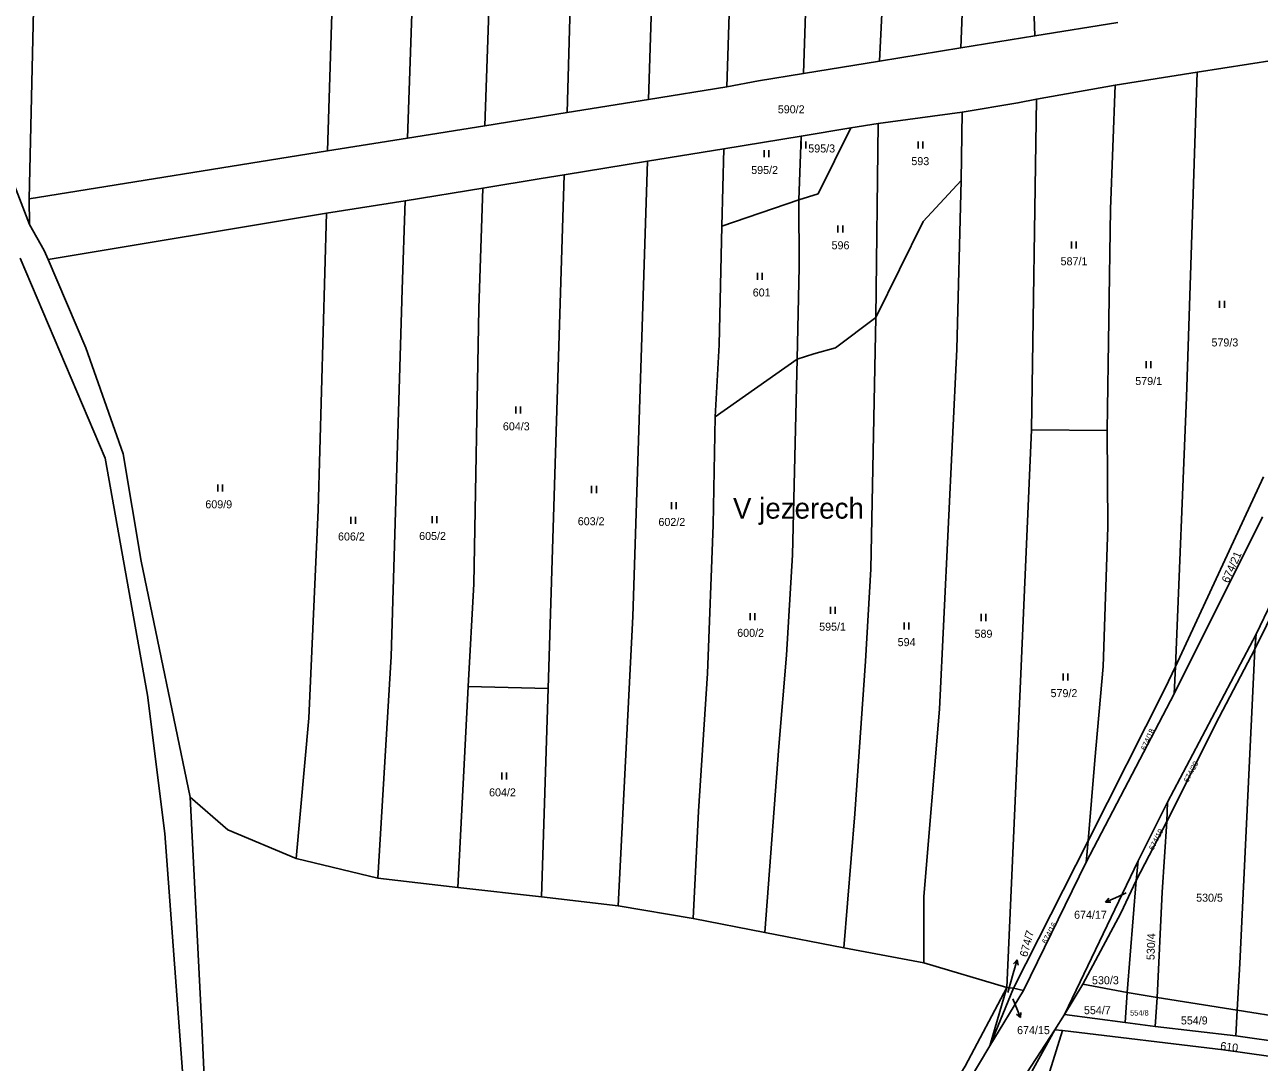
# Model space of a CAD drawing. Extents: x -7483133 to -743907, y -11317770 to -1129777.
# Drawn here: x -747219.6 to -746957.4, y -1132955.1 to -1132734.9 of the extents above; entities that cross this region are included whole.
import ezdxf

# ---------------------------------------------------------------- set-up
doc = ezdxf.new("R2010")
doc.units = 0
for name, color, linetype in [('Hranice parcel', 7, 'Continuous'), ('Parcelní čísla', 7, 'Continuous'), ('Pop  PČ popisy', 7, 'Continuous'), ('Značky kultur', 7, 'Continuous')]:
    doc.layers.add(name, color=color, linetype=linetype)

msp = doc.modelspace()

# ---------------------------------------------------------------- linework, layer by layer
at = {"layer": 'Hranice parcel'}
for p, q in [((-747020.76, -1132739.83), (-747018.91, -1132685.59)), ((-747005.69, -1132717.06), (-747005.08, -1132737.28)), ((-746987.48, -1132734.42), (-747005.08, -1132737.28)), ((-747005.08, -1132737.28), (-747020.76, -1132739.83)), ((-747020.76, -1132739.83), (-747038.08, -1132742.64)), ((-747038.08, -1132742.64), (-747054.23, -1132745.27)), ((-746970.6, -1132744.98), (-746954.26, -1132742.42)), ((-746970.6, -1132744.98), (-746988.01, -1132747.72)), ((-747070.51, -1132748.09), (-747087.14, -1132750.76)), ((-747004.75, -1132750.71), (-746988.01, -1132747.72)), ((-747087.14, -1132750.76), (-747104.4, -1132753.53)), ((-747004.75, -1132750.71), (-747005.78, -1132820.86)), ((-747104.4, -1132753.53), (-747121.84, -1132756.33)), ((-747038.33, -1132755.85), (-747020.5, -1132753.47)), ((-747020.5, -1132753.47), (-747020.75, -1132767.99)), ((-747121.84, -1132756.33), (-747138.3, -1132758.97)), ((-747054.69, -1132758.53), (-747044.17, -1132756.81)), ((-747044.17, -1132756.81), (-747038.33, -1132755.85)), ((-747038.33, -1132755.85), (-747038.87, -1132797.03)), ((-747138.3, -1132758.97), (-747155.28, -1132761.69)), ((-747071.09, -1132761.21), (-747054.69, -1132758.53)), ((-747055.16, -1132772.06), (-747054.69, -1132758.53)), ((-747155.28, -1132761.69), (-747218.59, -1132771.84)), ((-747087.3, -1132763.86), (-747071.09, -1132761.21)), ((-747071.09, -1132761.21), (-747071.52, -1132777.64)), ((-747105, -1132766.76), (-747087.3, -1132763.86)), ((-747105, -1132766.76), (-747108.42, -1132875.75)), ((-747138.77, -1132772.3), (-747122.29, -1132769.59)), ((-747218.53, -1132777.27), (-747218.59, -1132771.84)), ((-747218.53, -1132777.27), (-747218.59, -1132771.84)), ((-747155.49, -1132774.88), (-747138.77, -1132772.3)), ((-747071.52, -1132777.64), (-747055.16, -1132772.06)), ((-747214.61, -1132784.76), (-747155.49, -1132774.88)), ((-747055.52, -1132805.9), (-747072.95, -1132818.12)), ((-746989.74, -1132821.02), (-747005.78, -1132820.86)), ((-746939.25, -1132824.92), (-746958.1, -1132864.23)), ((-746975.22, -1132871.09), (-746956.52, -1132830.88)), ((-746975.46, -1132876.91), (-746956.71, -1132839.31)), ((-746958.1, -1132864.23), (-746976.89, -1132899.93)), ((-746958.34, -1132867.4), (-746958.1, -1132864.23)), ((-746975.46, -1132876.91), (-746975.22, -1132871.09)), ((-747125.41, -1132875.32), (-747127.61, -1132917.98)), ((-747108.42, -1132875.75), (-747125.41, -1132875.32)), ((-747108.42, -1132875.75), (-747109.82, -1132920.01)), ((-746994.16, -1132912.66), (-746975.46, -1132876.91)), ((-746976.89, -1132899.93), (-746983.14, -1132912.37)), ((-746977.03, -1132904.03), (-746976.89, -1132899.93)), ((-746977.03, -1132904.03), (-746983.53, -1132916.54)), ((-747009.63, -1132939.39), (-746993.77, -1132908.08)), ((-746994.16, -1132912.66), (-746993.77, -1132908.08)), ((-747144.6, -1132916.05), (-747161.9, -1132911.88)), ((-747144.6, -1132916.05), (-747161.9, -1132911.88)), ((-746983.14, -1132912.37), (-746998.8, -1132944.96)), ((-746983.53, -1132916.54), (-746983.14, -1132912.37)), ((-747007.45, -1132939.85), (-746994.16, -1132912.66)), ((-747127.61, -1132917.98), (-747144.6, -1132916.05)), ((-747127.61, -1132917.98), (-747144.6, -1132916.05)), ((-746985.48, -1132940.33), (-746983.53, -1132916.54)), ((-747109.82, -1132920.01), (-747127.61, -1132917.98)), ((-747109.82, -1132920.01), (-747127.61, -1132917.98)), ((-747093.54, -1132921.87), (-747109.82, -1132920.01)), ((-747093.54, -1132921.87), (-747109.82, -1132920.01)), ((-747077.64, -1132924.62), (-747093.54, -1132921.87)), ((-747077.64, -1132924.62), (-747093.54, -1132921.87)), ((-747062.38, -1132927.59), (-747077.64, -1132924.62)), ((-747062.38, -1132927.59), (-747077.64, -1132924.62)), ((-747045.65, -1132930.85), (-747062.38, -1132927.59)), ((-747045.65, -1132930.85), (-747062.38, -1132927.59)), ((-747028.66, -1132933.97), (-747045.65, -1132930.85)), ((-747028.66, -1132933.97), (-747045.65, -1132930.85)), ((-747011.03, -1132939.22), (-747028.66, -1132933.97)), ((-747011.03, -1132939.22), (-747028.66, -1132933.97)), ((-746994.87, -1132938.51), (-746998.8, -1132944.96)), ((-746994.87, -1132938.51), (-746985.48, -1132940.33)), ((-747014.63, -1132951.61), (-747011.03, -1132939.22)), ((-747014.63, -1132951.61), (-747011.03, -1132939.22)), ((-747014.63, -1132951.61), (-747009.63, -1132939.39)), ((-747014.63, -1132951.61), (-747007.45, -1132939.85)), ((-747009.63, -1132939.39), (-747011.03, -1132939.22)), ((-747007.45, -1132939.85), (-747009.63, -1132939.39)), ((-746985.9, -1132946.64), (-746985.48, -1132940.33)), ((-746985.48, -1132940.33), (-746979.06, -1132941.33)), ((-746979.52, -1132947.54), (-746979.06, -1132941.33)), ((-746979.06, -1132941.33), (-746962.08, -1132944.03)), ((-746962.38, -1132949.49), (-746962.08, -1132944.03)), ((-746962.08, -1132944.03), (-746944.33, -1132946.92)), ((-746998.8, -1132944.96), (-747000.79, -1132948.22)), ((-746985.9, -1132946.64), (-746998.8, -1132944.96)), ((-746979.52, -1132947.54), (-746985.9, -1132946.64)), ((-747000.79, -1132948.22), (-746999.22, -1132948.35)), ((-746962.38, -1132949.49), (-746979.52, -1132947.54)), ((-746943.99, -1132952.09), (-746962.38, -1132949.49))]:
    msp.add_line(p, q, dxfattribs=at)
for points in [[(-747038.08, -1132742.64), (-747034.84, -1132678.24), (-747033.64, -1132597.08), (-747031.93, -1132533.05), (-747029.51, -1132463.38), (-747028.52, -1132416.99), (-747027.87, -1132347.05), (-747027.28, -1132293.41)], [(-747076.79, -1132295.83), (-747078.66, -1132390.05), (-747080.33, -1132467.43), (-747083.61, -1132583.5), (-747084.89, -1132682.58), (-747087.14, -1132750.76)], [(-747060.43, -1132295.27), (-747061.53, -1132332.94), (-747062.8, -1132413.73), (-747065.53, -1132535.08), (-747067.23, -1132623.45), (-747068.09, -1132673.14), (-747070.51, -1132748.09)], [(-747044.14, -1132294.41), (-747045.39, -1132378.05), (-747045.42, -1132402.53), (-747048.2, -1132503.11), (-747049.83, -1132575.85), (-747052.26, -1132674.28), (-747053.27, -1132717.53), (-747054.23, -1132745.27)], [(-747126.8, -1132298.51), (-747129.46, -1132399.59), (-747131.89, -1132510.66), (-747134.02, -1132600.6), (-747135.16, -1132669.57), (-747138.3, -1132758.97)], [(-747109.65, -1132297.48), (-747112.78, -1132422), (-747115.35, -1132508.1), (-747118.49, -1132631.03), (-747119.2, -1132688.28), (-747120.52, -1132717.76), (-747121.84, -1132756.33)], [(-747092.43, -1132296.62), (-747093.64, -1132322.66), (-747095.93, -1132401.18), (-747098.72, -1132517.12), (-747102.15, -1132640.46), (-747102.28, -1132678.3), (-747104.4, -1132753.53)], [(-747295.89, -1132582.7), (-747279.64, -1132623.02), (-747268.86, -1132651.49), (-747237.8, -1132727.36), (-747218.53, -1132777.27)], [(-747218.59, -1132771.84), (-747217.53, -1132725.58), (-747209.76, -1132658.63), (-747207.17, -1132631.63), (-747205.5, -1132602.3)], [(-747218.59, -1132771.84), (-747217.53, -1132725.58), (-747209.76, -1132658.63), (-747207.17, -1132631.63), (-747205.5, -1132602.3)], [(-747151.14, -1132604.73), (-747153.57, -1132707.96), (-747155.28, -1132761.69)], [(-747054.23, -1132745.27), (-747063.77, -1132746.82), (-747070.51, -1132748.09)], [(-746975.22, -1132871.09), (-746972.88, -1132813.95), (-746970.6, -1132744.98)], [(-746988.01, -1132747.72), (-746989.02, -1132774.05), (-746989.74, -1132821.02)], [(-747020.5, -1132753.47), (-747008.66, -1132751.51), (-747004.75, -1132750.71)], [(-747055.16, -1132772.06), (-747051.09, -1132770.78), (-747044.17, -1132756.81)], [(-747087.3, -1132763.86), (-747090.45, -1132860.47), (-747093.54, -1132921.87)], [(-747122.29, -1132769.59), (-747109.91, -1132767.56), (-747105, -1132766.76)], [(-747038.87, -1132797.03), (-747028.78, -1132776.67), (-747020.75, -1132767.99)], [(-747020.75, -1132767.99), (-747021.62, -1132803.73), (-747025.3, -1132880.13), (-747028.61, -1132919.93), (-747028.66, -1132933.97)], [(-747122.29, -1132769.59), (-747123.16, -1132795.15), (-747124.23, -1132853.55), (-747125.41, -1132875.32)], [(-747138.77, -1132772.3), (-747139.43, -1132791.06), (-747141.72, -1132869.02), (-747144.6, -1132916.05)], [(-747055.16, -1132772.06), (-747055.09, -1132786.27), (-747055.52, -1132805.9)], [(-747155.49, -1132774.88), (-747157.25, -1132837.88), (-747159.22, -1132882.07), (-747161.9, -1132911.88)], [(-747214.61, -1132784.76), (-747215.45, -1132782.81), (-747218.53, -1132777.27)], [(-747214.61, -1132784.76), (-747215.45, -1132782.81), (-747218.53, -1132777.27)], [(-747071.52, -1132777.64), (-747072.09, -1132802.85), (-747072.95, -1132818.12)], [(-747180.82, -1133032.94), (-747182.45, -1133006.42), (-747183.17, -1132996.67), (-747184.46, -1132979.1), (-747185.65, -1132962.8), (-747189.83, -1132906.57), (-747193.53, -1132877.19), (-747202.48, -1132826.92), (-747220.56, -1132784.45)], [(-747184.42, -1132898.81), (-747194.87, -1132848.77), (-747198.69, -1132825.98), (-747206.6, -1132803.47), (-747214.61, -1132784.76)], [(-747184.42, -1132898.81), (-747194.87, -1132848.77), (-747198.69, -1132825.98), (-747206.6, -1132803.47), (-747214.61, -1132784.76)], [(-747038.87, -1132797.03), (-747047.41, -1132803.47), (-747051.98, -1132804.76), (-747055.52, -1132805.9)], [(-747045.65, -1132930.85), (-747043.29, -1132902.39), (-747041, -1132869.99), (-747039.87, -1132850.43), (-747038.87, -1132797.03)], [(-747055.52, -1132805.9), (-747056.55, -1132847.44), (-747057.84, -1132868.71), (-747059.41, -1132888.12), (-747062.38, -1132927.59)], [(-747072.95, -1132818.12), (-747073.37, -1132841.04), (-747074.58, -1132872.59), (-747076.51, -1132901.8), (-747077.64, -1132924.62)], [(-747005.78, -1132820.86), (-747008.05, -1132872.67), (-747011.03, -1132939.22)], [(-746989.74, -1132821.02), (-746989.6, -1132841.57), (-746990.59, -1132871.12), (-746992.31, -1132890.96), (-746993.77, -1132908.08)], [(-746939.21, -1132828.21), (-746943.35, -1132836.99), (-746958.34, -1132867.4)], [(-746958.34, -1132867.4), (-746965.9, -1132881.89), (-746977.03, -1132904.03)], [(-746962.08, -1132944.03), (-746961.54, -1132934.15), (-746958.34, -1132867.4)], [(-746993.77, -1132908.08), (-746977.37, -1132875.71), (-746975.22, -1132871.09)], [(-747161.9, -1132911.88), (-747176.42, -1132905.74), (-747184.42, -1132898.81)], [(-747161.9, -1132911.88), (-747176.42, -1132905.74), (-747184.42, -1132898.81)], [(-747184.42, -1132898.81), (-747181.92, -1132948.88), (-747179.76, -1132996)], [(-746979.06, -1132941.33), (-746978.06, -1132919.01), (-746977.03, -1132904.03)], [(-746983.53, -1132916.54), (-746986.81, -1132923.44), (-746994.87, -1132938.51)], [(-747064.03, -1133027.44), (-747036.92, -1132983.8), (-747019.89, -1132955.94), (-747011.03, -1132939.22)], [(-747000.79, -1132948.22), (-747011.62, -1132964.83), (-747060.85, -1133045.72), (-747119.18, -1133136.56)], [(-747000.79, -1132948.22), (-747024.69, -1132991.47), (-747060.4, -1133049.29), (-747085.54, -1133089.77)], [(-747063.59, -1133061.56), (-747032.47, -1133013.67), (-747008.28, -1132977.41), (-746999.22, -1132948.35)], [(-746999.22, -1132948.35), (-746965.02, -1132952.48), (-746930.34, -1132957.34)], [(-747082.43, -1133061.55), (-747077.79, -1133057.43), (-747045.76, -1133015.45), (-747039.19, -1132997.18), (-747033.02, -1132982.46), (-747014.63, -1132951.61)], [(-747082.43, -1133061.55), (-747077.79, -1133057.43), (-747045.76, -1133015.45), (-747039.19, -1132997.18), (-747033.02, -1132982.46), (-747014.63, -1132951.61)]]:
    msp.add_lwpolyline(points, dxfattribs=at)
at = {"layer": 'Pop  PČ popisy'}
for p, q in [((-746987.34, -1132919.89), (-746990.08, -1132921.11)), ((-746990.08, -1132921.11), (-746989.37, -1132920.25)), ((-746985.71, -1132919.16), (-746987.34, -1132919.89)), ((-746990.08, -1132921.11), (-746988.96, -1132921.16)), ((-747009.64, -1132936.26), (-747008.81, -1132933.38)), ((-747008.81, -1132933.38), (-747009.57, -1132934.2)), ((-747008.81, -1132933.38), (-747008.61, -1132934.48)), ((-747010.78, -1132940.28), (-747009.64, -1132936.26)), ((-747009.77, -1132941.63), (-747009.27, -1132942.85)), ((-747009.27, -1132942.85), (-747008.15, -1132945.63)), ((-747008.15, -1132945.63), (-747008.98, -1132944.89)), ((-747008.15, -1132945.63), (-747008.06, -1132944.52))]:
    msp.add_line(p, q, dxfattribs=at)
at = {"layer": 'Značky kultur'}
for p, q in [((-747054.69, -1132761.16), (-747054.69, -1132759.66)), ((-747053.69, -1132761.16), (-747053.69, -1132759.66)), ((-747029.86, -1132761.15), (-747029.86, -1132759.65)), ((-747028.86, -1132761.15), (-747028.86, -1132759.65)), ((-747062.53, -1132763.03), (-747062.53, -1132761.53)), ((-747061.53, -1132763.03), (-747061.53, -1132761.53)), ((-747046.87, -1132779.01), (-747046.87, -1132777.51)), ((-747045.87, -1132779.01), (-747045.87, -1132777.51)), ((-746997.26, -1132782.4), (-746997.26, -1132780.9)), ((-746996.26, -1132782.4), (-746996.26, -1132780.9)), ((-747063.94, -1132789.03), (-747063.94, -1132787.53)), ((-747062.94, -1132789.03), (-747062.94, -1132787.53)), ((-746965.83, -1132794.97), (-746965.83, -1132793.47)), ((-746964.83, -1132794.97), (-746964.83, -1132793.47)), ((-746981.42, -1132807.82), (-746981.42, -1132806.32)), ((-746980.42, -1132807.82), (-746980.42, -1132806.32)), ((-747115.31, -1132817.43), (-747115.31, -1132815.93)), ((-747114.31, -1132817.43), (-747114.31, -1132815.93)), ((-747178.57, -1132833.98), (-747178.57, -1132832.48)), ((-747177.57, -1132833.98), (-747177.57, -1132832.48)), ((-747099.18, -1132834.29), (-747099.18, -1132832.79)), ((-747098.18, -1132834.29), (-747098.18, -1132832.79)), ((-747082.23, -1132837.73), (-747082.23, -1132836.23)), ((-747081.23, -1132837.73), (-747081.23, -1132836.23)), ((-747150.33, -1132840.82), (-747150.33, -1132839.32)), ((-747149.33, -1132840.82), (-747149.33, -1132839.32)), ((-747133.06, -1132840.71), (-747133.06, -1132839.21)), ((-747132.06, -1132840.71), (-747132.06, -1132839.21)), ((-747065.54, -1132861.27), (-747065.54, -1132859.77)), ((-747064.54, -1132861.27), (-747064.54, -1132859.77)), ((-747048.47, -1132859.96), (-747048.47, -1132858.46)), ((-747047.47, -1132859.96), (-747047.47, -1132858.46)), ((-747016.49, -1132861.46), (-747016.49, -1132859.96)), ((-747015.49, -1132861.46), (-747015.49, -1132859.96)), ((-747032.84, -1132863.24), (-747032.84, -1132861.74)), ((-747031.84, -1132863.24), (-747031.84, -1132861.74)), ((-746999.04, -1132874.06), (-746999.04, -1132872.56)), ((-746998.04, -1132874.06), (-746998.04, -1132872.56)), ((-747118.25, -1132895.12), (-747118.25, -1132893.62)), ((-747117.25, -1132895.12), (-747117.25, -1132893.62))]:
    msp.add_line(p, q, dxfattribs=at)

# ---------------------------------------------------------------- texts
at = {"layer": 'Parcelní čísla'}
for s, height, p in [('590/2', 1.7, (-747059.65, -1132753.7)), ('595/3', 1.7, (-747053.18, -1132762.01)), ('593', 1.7, (-747031.29, -1132764.7)), ('595/2', 1.7, (-747065.3, -1132766.58)), ('596', 1.7, (-747048.23, -1132782.56)), ('587/1', 1.7, (-746999.6, -1132785.95)), ('601', 1.7, (-747064.97, -1132792.58)), ('579/3', 1.7, (-746967.56, -1132803.18)), ('579/1', 1.7, (-746983.74, -1132811.37)), ('604/3', 1.7, (-747118.03, -1132820.98)), ('609/9', 1.7, (-747181.21, -1132837.53)), ('603/2', 1.7, (-747102.13, -1132841.13)), ('602/2', 1.7, (-747085, -1132841.28)), ('606/2', 1.7, (-747153.04, -1132844.37)), ('605/2', 1.7, (-747135.81, -1132844.26)), ('595/1', 1.7, (-747050.87, -1132863.51)), ('600/2', 1.7, (-747068.27, -1132864.82)), ('594', 1.7, (-747034.2, -1132866.79)), ('589', 1.7, (-747017.87, -1132865.01)), ('579/2', 1.7, (-747001.73, -1132877.61)), ('604/2', 1.7, (-747120.96, -1132898.67)), ('530/5', 1.7, (-746970.82, -1132921.03)), ('674/17', 1.7, (-746996.74, -1132924.65)), ('530/3', 1.7, (-746992.93, -1132938.55)), ('554/7', 1.7, (-746994.64, -1132944.9)), ('554/8', 1.14, (-746984.84, -1132945.2)), ('554/9', 1.7, (-746974.06, -1132947.08)), ('674/15', 1.7, (-747008.84, -1132949.14))]:
    msp.add_text(s, height=height, dxfattribs=at).set_placement(p)
for s, height, rotation, p in [('674/21', 1.7, 66, (-746963.93, -1132853.52)), ('674/18', 1.14, 66, (-746981.58, -1132889.02)), ('674/20', 1.14, 62, (-746972.55, -1132895.85)), ('674/19', 1.14, 63, (-746979.91, -1132910.22)), ('674/16', 1.14, 62, (-747002.63, -1132930.06)), ('674/7', 1.7, 75, (-747006.7, -1132932.88)), ('530/4', 1.7, 88, (-746979.67, -1132933.45)), ('610', 1.7, 353, (-746965.77, -1132952.44))]:
    msp.add_text(s, height=height, rotation=rotation, dxfattribs=at).set_placement(p)
at = {"layer": 'Pop  PČ popisy'}
msp.add_text('V jezerech', height=4.4, dxfattribs=at).set_placement((-747069.17, -1132839.73))

doc.saveas('drawing.dxf')
